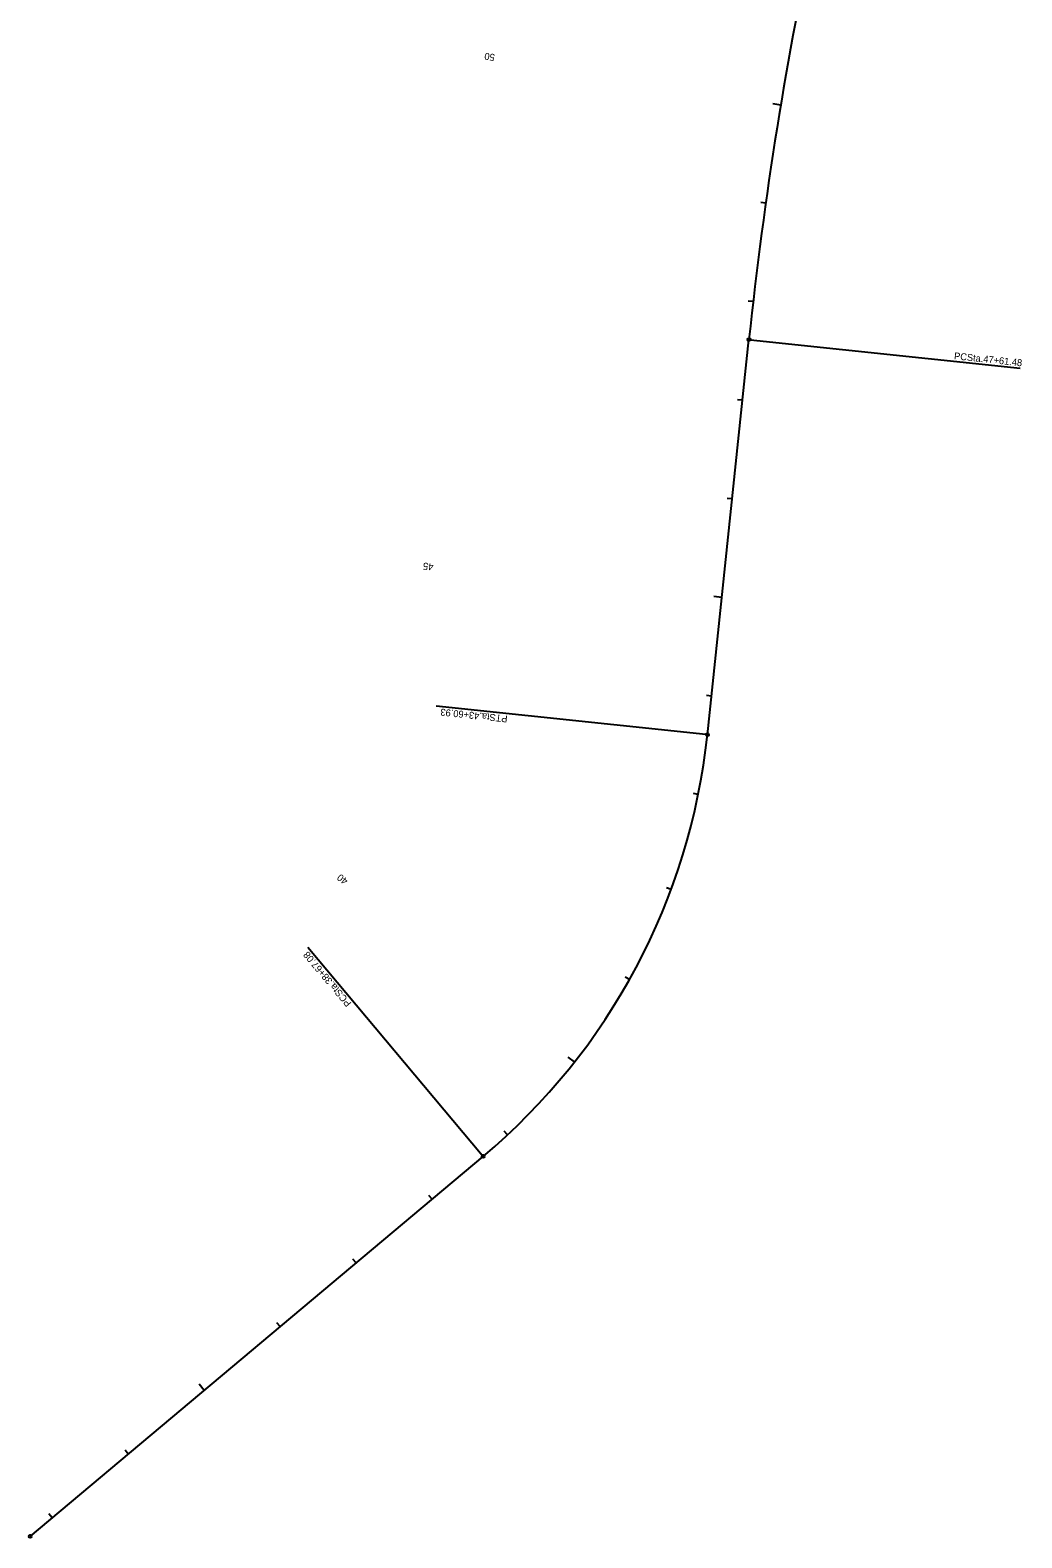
# Model space of a CAD drawing. Extents: x 554184 to 558768, y 503077 to 507235.
# Drawn here: x 556427 to 557427, y 504162 to 505683 of the extents above; entities that cross this region are included whole.
import ezdxf

# ---------------------------------------------------------------- set-up
doc = ezdxf.new("R2010")
doc.units = 0
for name, color, linetype in [('Default', 7, 'Continuous'), ('Prop Horizontal Alignment Station Label', 7, 'Continuous'), ('Prop Horizontal Alignment Tick Label', 7, 'Continuous'), ('Prop Horizontal Alignment Tick Large', 7, 'Continuous'), ('Prop Horizontal Alignment Tick Small', 7, 'Continuous'), ('Prop Vertical Profile Grade', 7, 'Continuous')]:
    doc.layers.add(name, color=color, linetype=linetype)

msp = doc.modelspace()

# ---------------------------------------------------------------- linework, layer by layer
at = {"layer": 'Default'}
for p, q in [((557110.1, 504972.3), (557152, 505370.7)), ((556427, 504163.9), (556883.8, 504547))]:
    msp.add_line(p, q, dxfattribs=at)
for centre, radius, start, end in [((561130, 504951.7), 4000, 161.6362, 173.9875), ((556470.6, 505039.7), 643, 309.9822, 353.9875)]:
    msp.add_arc(centre, radius, start, end, dxfattribs=at)
at = {"layer": 'Prop Horizontal Alignment Station Label'}
for p, q in [((557153.5, 505370.5), (557425.5, 505341.9)), ((557108.6, 504972.5), (556836.6, 505001.1)), ((556882.8, 504548.1), (556707.1, 504757.7))]:
    msp.add_line(p, q, dxfattribs=at)
for centre in [(557152, 505370.7), (557110.1, 504972.3), (556883.8, 504547), (556427, 504163.9)]:
    msp.add_circle(centre, 1.5, dxfattribs=at)
at = {"layer": 'Prop Horizontal Alignment Tick Large'}
for p, q in [((557184.1, 505607), (557176.2, 505608.3)), ((557124.6, 505110.6), (557116.7, 505111.5)), ((556976.1, 504642.3), (556969.8, 504647.2)), ((556602.5, 504311.1), (556597.4, 504317.3))]:
    msp.add_line(p, q, dxfattribs=at)
at = {"layer": 'Prop Horizontal Alignment Tick Small'}
for p, q in [((557168.9, 505508.2), (557164, 505508.9)), ((557156.3, 505409), (557151.3, 505409.5)), ((557145.6, 505309.5), (557140.6, 505310.1)), ((557135.1, 505210.1), (557130.1, 505210.6)), ((557114.2, 505011.2), (557109.2, 505011.7)), ((557100.8, 504912.1), (557095.9, 504913.1)), ((557073.5, 504816.1), (557068.8, 504817.8)), ((557031.6, 504725.4), (557027.2, 504727.8)), ((556908.4, 504568.8), (556905, 504572.4)), ((556832.4, 504503.9), (556829.2, 504507.7)), ((556755.8, 504439.6), (556752.5, 504443.5)), ((556679.1, 504375.4), (556675.9, 504379.2)), ((556525.9, 504246.9), (556522.7, 504250.7)), ((556449.3, 504182.6), (556446, 504186.5))]:
    msp.add_line(p, q, dxfattribs=at)
at = {"layer": 'Prop Vertical Profile Grade'}
for p, q in [((557110.1, 504972.3), (557152, 505370.7)), ((556427, 504163.9), (556883.8, 504547))]:
    msp.add_line(p, q, dxfattribs=at)
for centre, radius, start, end in [((561130, 504951.7), 4000, 161.6362, 173.9875), ((556470.6, 505039.7), 643, 309.9822, 353.9875)]:
    msp.add_arc(centre, radius, start, end, dxfattribs=at)

# ---------------------------------------------------------------- texts
at = {"layer": 'Prop Horizontal Alignment Station Label'}
for s, rotation, p in [('PCSta.47+61.48', 353.9875, (557358.6, 505350.9)), ('PTSta.43+60.93', 173.9875, (556908.8, 504991.5)), ('PCSta.38+67.08', 129.9822, (556751.5, 504701.6))]:
    msp.add_text(s, height=7, rotation=rotation, dxfattribs=at).set_placement(p)
at = {"layer": 'Prop Horizontal Alignment Tick Label'}
for s, rotation, p in [('50', 170.5709, (556896.1, 505658.4)), ('45', 173.9875, (556834, 505144.8)), ('40', 141.8262, (556748.2, 504825.9))]:
    msp.add_text(s, height=7, rotation=rotation, dxfattribs=at).set_placement(p)

doc.saveas('drawing.dxf')
